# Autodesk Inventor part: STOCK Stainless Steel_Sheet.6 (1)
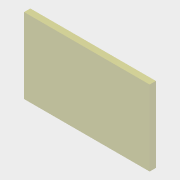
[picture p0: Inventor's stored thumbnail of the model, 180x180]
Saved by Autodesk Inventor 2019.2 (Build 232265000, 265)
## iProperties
Created: 2019-02
Part Number: STOCK Stainless Steel_Sheet.6 (1)
Material: Stainless Steel
Document SubType Name: Modeling
Designer: User
Density: 8 g/cm^3
Appearance: Semi-Polished
Author: User
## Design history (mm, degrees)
sketch "STOCK Stainless Steel sketch"
  geometry: L1 (0, 0)-(0, 76.2); L2 (0, 76.2)-(127, 76.2); L3 (127, 76.2)-(127, 0); L4 (127, 0)-(0, 0)
  constraints: 8 end point
extrude "STOCK Stainless Steel extrude" new body sketch "STOCK Stainless Steel sketch" distance "d0" = 6.34; taper "d1" = 0 deg
node "STOCK Stainless Steel"
